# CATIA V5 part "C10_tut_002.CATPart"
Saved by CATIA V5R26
Part number: Part1
Bounding box of the stored display mesh (mm): x -105 to 105, y -154.964 to 550, z -23.67 to 23.672
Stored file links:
  D:\_Deepak\CATIA\CATIA V5 2015 Parts Files\Tutorial Files\Tutorials\c10_catia_v5_6r2015_tut\C10_tut_002.CATPart
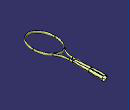
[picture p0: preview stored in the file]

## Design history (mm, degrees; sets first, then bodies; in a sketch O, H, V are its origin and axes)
Body1 (main body)
  Sketch1 on xy-plane, origin (0, 0, 0), H (1, 0, 0), V (0, 1, 0)
    ellipse A1 centre (0, 0) semi-axes 100, 150 rotation 0
    point P1 (100, 0)
    point P2 (-100, 0)
    "Radius" A1 = 100
    "Radius" A1 = 150
    "Radius" A1 = 100 (reference)
    coincidence: P1 H, A1 P1, P2 A1, P2 H
    perpendicularity: A1 V
  Sketch2 on zx-plane, origin (0, 0, 0), H (-1, 0, 0), V (0, 0, 1)
    point P1 (100, 0)
    ellipse A1 centre (100, 0) semi-axes 10, 5 rotation 270
    reference projected point E1 (100, 0) from Sketch1.P2
    "Radius" A1 = 10
    "Radius" A1 = 5
    coincidence: P1 H, P1 E1
  Sweep1: type Unspec, Profile Sketch2, Guide Sketch1.A1
  Sketch3 on xy-plane, origin (0, 0, 0), H (1, 0, 0), V (0, 1, 0)
    line L1 (15, 245) -> (15, 275)
    point P2 (15, 275)
    arc A1 centre (215, 245) radius 200 from (15, 245) to (55, 125) ccw
    point P4 (55, 125)
    distance L1 V = 15
    distance P2 H = 275
    radius A1 = 200
    distance P4 V = 55
    distance P4 H = 125
    tangency: L1 A1
  Plane1: type Normal, Curve Sketch3, RefPoint Sketch3.P2, Ratio 0
  Sketch4 on Plane1, origin (0, 275, 0), H (1, 0, 0), V (0, 0, 1)
    point P1 (15, 0)
    ellipse A1 centre (15, 0) semi-axes 8.75, 4.5 rotation 270
    reference projected point E1 (15, 0) from Sketch3.P2
    "Radius" A1 = 8.75
    "Radius" A1 = 4.5
    coincidence: P1 H, P1 E1
  Sweep2: type Unspec, Profile Sketch4, Guide Sketch3
  Symmetry1: ToTransfor Sweep2, Reference yz-plane
  Trim1: Trimmed (Symmetry1; Sweep1)
  Trim2: Trimmed (Sweep2; Trim1)
  Sketch5 on Plane1, origin (0, 275, 0), H (1, 0, 0), V (0, 0, 1)
    projected curve E1 from edge of Sweep2
    projected curve E2 from edge of Sweep2
    projected curve E3 from edge of Symmetry1
    projected curve E4 from edge of Symmetry1
    line L1 (11.75, 6.052) -> (-11.75, 6.052)
    point P1 (11.75, 6.052)
    point P2 (-11.75, 6.052)
    reference intersected line E5 through (0, 0) direction (-1, 0) from xy-plane
    point P5 (-11.75, -6.052)
    point P6 (11.75, -6.052)
    line L2 (11.75, -6.052) -> (-11.75, -6.052)
    point P7 (-11.75, -6.052)
    point P8 (11.75, -6.052)
    length L1 = 23.5
    coincidence: P1 E1, P2 E3, L2 P7, L2 P8
    horizontal: L1 H
    symmetry: P2 P5 E5, P1 P6 E5, L1 L2 E5
  Plane2: type Offset, RefPlane zx-plane, Offset 425
  Sketch6 on Plane2, origin (0, 425, 0), H (-1, 0, 0), V (0, 0, 1)
    ellipse A1 centre (0, 0) semi-axes 22.5, 20 rotation 0
    point P1 (22.5, 0)
    point P2 (-11.75, 17.0562)
    point P3 (11.75, 17.0562)
    point P4 (11.75, -17.0562)
    point P5 (-11.75, -17.0562)
    "Radius" A1 = 22.5
    "Radius" A1 = 20
    distance P2 P3 = 23.5
    distance P2 V = 11.75
    distance P5 V = 11.75
    distance P4 P5 = 23.5
    distance P3 P4 = 34.1124
    coincidence: P1 H, A1 P1, P2 A1, P3 A1, P4 A1, P5 A1
  Loft1: Sections (Sketch5; Sketch6.A1), SectionCouplingPoints ({coupling CouplingPoints (vertex [element of Sketch5 | element of Sketch5]; Sketch6.P2)}; {coupling CouplingPoints (vertex [element of Sketch5 | element of Sketch5]; Sketch6.P5)}; {coupling CouplingPoints (vertex [element of Sketch5 | element of Sketch5]; Sketch6.P3)}; {coupling CouplingPoints (vertex [element of Sketch5 | element of Sketch5]; Sketch6.P4)})
  Plane3: type Offset, RefPlane zx-plane, Offset 550
  Sketch7 on Plane3, origin (0, 550, 0), H (-1, 0, 0), V (0, 0, 1)
    circle A1 centre (0, 0) radius 22.5
    radius A1 = 22.5
  Blend1: StartLimit {blendlimit Curve Sketch6.A1, Point {extremum Reference Sketch6.A1, Direction (1, 2, 3)}, Support Loft1}, EndLimit {blendlimit Curve Sketch7, Point {extremum Reference Sketch7, Direction (1, 2, 3)}}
